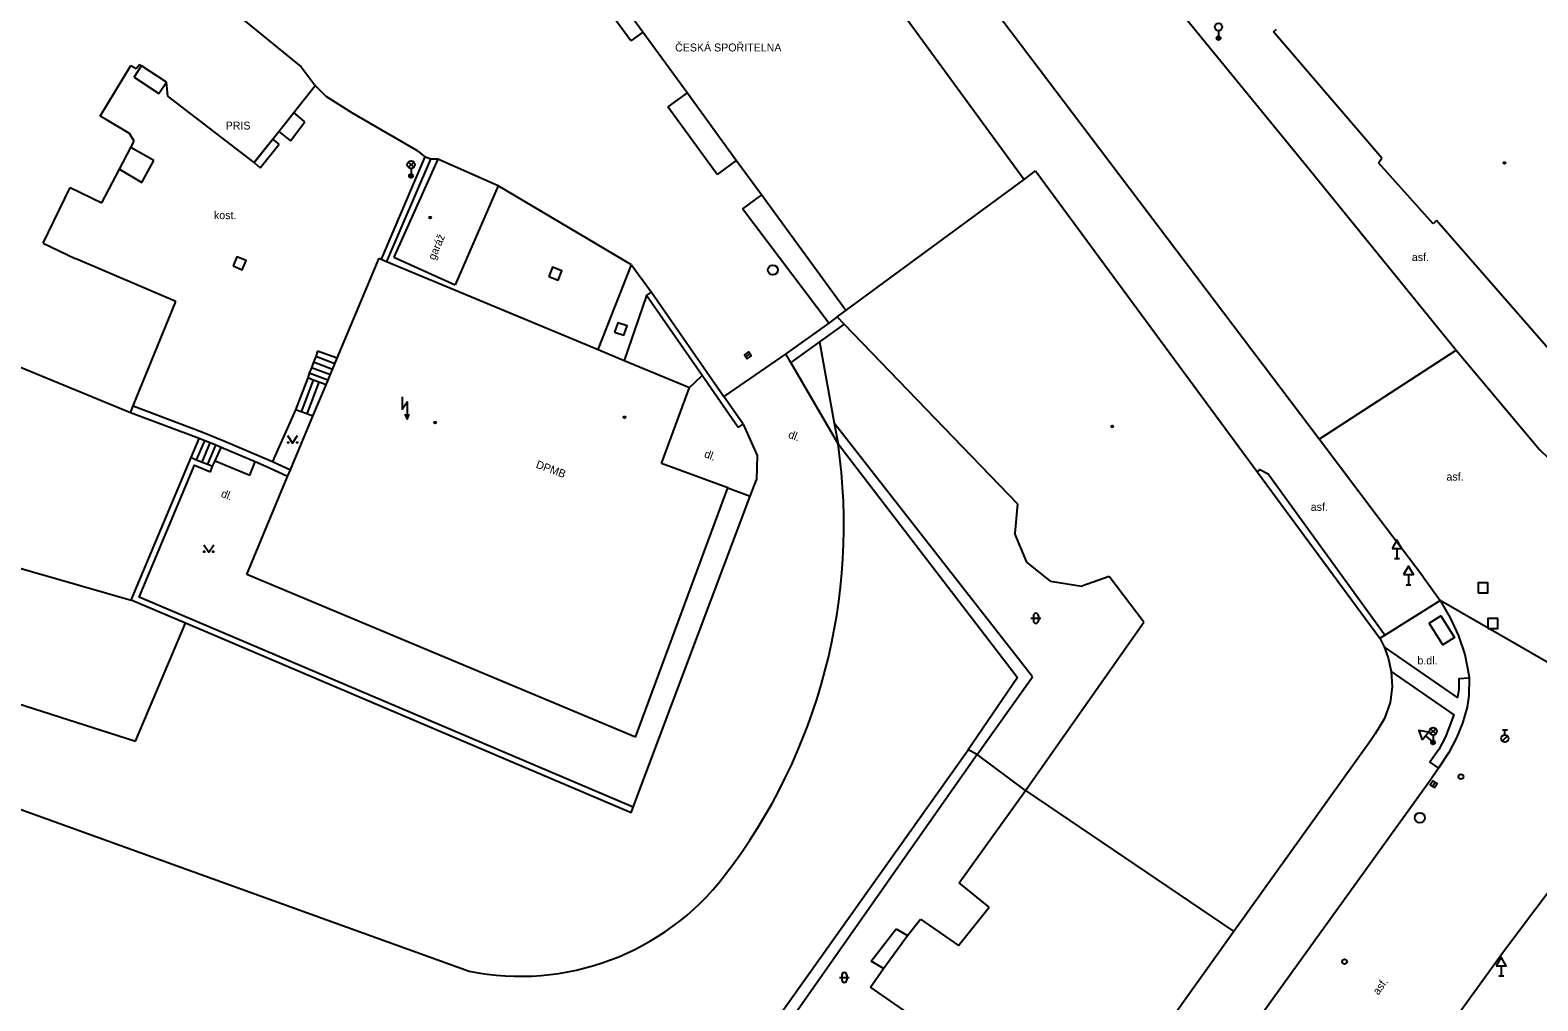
# Model space of a CAD drawing. Extents: x -599770 to -598493, y -1162076 to -1159209.
# Drawn here: x -599223.2 to -599147.3, y -1161433.6 to -1161384.7 of the extents above; entities that cross this region are included whole.
import ezdxf

# ---------------------------------------------------------------- set-up
doc = ezdxf.new("R2010")
doc.units = 0
doc.layers.add('Podklad', color=7, linetype='Continuous')

msp = doc.modelspace()

# ---------------------------------------------------------------- linework, layer by layer
at = {"layer": 'Podklad'}
for p, q in [((-599163.36, -1161384.765), (-599163.36, -1161385.14)), ((-599204.133, -1161391.64), (-599203.868, -1161391.375)), ((-599204.133, -1161391.375), (-599203.868, -1161391.64)), ((-599204, -1161391.695), (-599204, -1161392.07)), ((-599187.151, -1161401.174), (-599186.949, -1161401.026)), ((-599154.38, -1161410.821), (-599154.38, -1161411.33)), ((-599154.505, -1161411.33), (-599154.255, -1161411.33)), ((-599153.8, -1161412.141), (-599153.8, -1161412.65)), ((-599153.925, -1161412.65), (-599153.675, -1161412.65)), ((-599172.803, -1161414.338), (-599172.303, -1161414.338)), ((-599172.678, -1161414.213), (-599172.678, -1161414.463)), ((-599172.428, -1161414.213), (-599172.428, -1161414.463)), ((-599152.692, -1161420.16), (-599152.427, -1161419.895)), ((-599152.692, -1161419.895), (-599152.427, -1161420.16)), ((-599149.075, -1161419.953), (-599148.825, -1161419.953)), ((-599148.95, -1161420.203), (-599148.95, -1161419.953)), ((-599152.948, -1161420.261), (-599152.56, -1161420.59)), ((-599152.641, -1161420.685), (-599152.479, -1161420.495)), ((-599152.56, -1161420.215), (-599152.56, -1161420.59)), ((-599149.079, -1161420.526), (-599148.814, -1161420.261)), ((-599152.599, -1161422.795), (-599152.461, -1161422.585)), ((-599149.13, -1161431.831), (-599149.13, -1161432.34)), ((-599182.443, -1161432.418), (-599181.943, -1161432.418)), ((-599182.318, -1161432.293), (-599182.318, -1161432.543)), ((-599182.068, -1161432.293), (-599182.068, -1161432.543)), ((-599149.255, -1161432.34), (-599149.005, -1161432.34))]:
    msp.add_line(p, q, dxfattribs=at)
for points in [[(-599191.19, -1161352.2), (-599177.913, -1161368.369), (-599176.32, -1161370.31), (-599158.79, -1161391.75), (-599151.4, -1161400.84), (-599147.2, -1161405.85), (-599145.39, -1161407.58)], [(-599153.06, -1161412.26), (-599155.32, -1161409.26), (-599158.29, -1161405.32), (-599169.77, -1161390.15), (-599183.101, -1161372.518), (-599187.56, -1161366.62), (-599195.73, -1161355.8)], [(-599186.14, -1161374.45), (-599185.62, -1161375.163), (-599173.15, -1161392.26)], [(-599192.34, -1161384.84), (-599195.11, -1161381.05)], [(-599215.24, -1161381.92), (-599209.53, -1161386.58)], [(-599192.94, -1161385.28), (-599195.71, -1161381.49)], [(-599192.34, -1161384.84), (-599192.94, -1161385.28)], [(-599190.11, -1161387.89), (-599192.34, -1161384.84)], [(-599160.6, -1161384.82), (-599160.44, -1161384.68)], [(-599155.15, -1161391.18), (-599160.6, -1161384.82)], [(-599219.65, -1161389.07), (-599218.1, -1161386.52)], [(-599218.1, -1161386.52), (-599217.83, -1161386.67)], [(-599217.94, -1161387.1), (-599217.56, -1161386.53)], [(-599217.83, -1161386.67), (-599217.66, -1161386.46)], [(-599217.56, -1161386.53), (-599217.66, -1161386.46)], [(-599216.31, -1161387.36), (-599217.56, -1161386.53)], [(-599209.53, -1161386.58), (-599208.83, -1161387.52)], [(-599217.94, -1161387.1), (-599216.69, -1161387.92)], [(-599216.69, -1161387.92), (-599216.31, -1161387.36)], [(-599216.24, -1161388.06), (-599216.31, -1161387.36)], [(-599211.9, -1161391.4), (-599216.24, -1161388.06)], [(-599209.9, -1161388.88), (-599208.83, -1161387.52)], [(-599208.27, -1161388.08), (-599208.83, -1161387.52)], [(-599206.95, -1161388.91), (-599208.27, -1161388.08)], [(-599190.11, -1161387.89), (-599191.08, -1161388.6)], [(-599187.63, -1161391.29), (-599190.11, -1161387.89)], [(-599210.66, -1161389.84), (-599209.9, -1161388.88)], [(-599209.35, -1161389.35), (-599209.9, -1161388.88)], [(-599203.68, -1161390.81), (-599206.95, -1161388.91)], [(-599188.6, -1161392), (-599191.08, -1161388.6)], [(-599219.38, -1161389.22), (-599219.65, -1161389.07)], [(-599218.17, -1161389.94), (-599219.38, -1161389.22)], [(-599210.07, -1161390.31), (-599209.35, -1161389.35)], [(-599217.94, -1161390.32), (-599218.17, -1161389.94)], [(-599218.11, -1161390.64), (-599217.94, -1161390.32)], [(-599211.9, -1161391.4), (-599210.66, -1161389.84)], [(-599210.63, -1161390.48), (-599210.96, -1161390.22), (-599211.9, -1161391.4)], [(-599210.66, -1161389.84), (-599210.07, -1161390.31)], [(-599218.68, -1161391.73), (-599218.11, -1161390.64)], [(-599216.94, -1161391.29), (-599218.11, -1161390.64)], [(-599211.59, -1161391.66), (-599210.63, -1161390.48)], [(-599203.3, -1161391.12), (-599205.51, -1161396.26)], [(-599203.68, -1161390.81), (-599203.3, -1161391.12)], [(-599203.02, -1161391.23), (-599203.3, -1161391.12)], [(-599155.31, -1161391.42), (-599155.15, -1161391.18)], [(-599219.56, -1161393.43), (-599218.68, -1161391.73)], [(-599218.68, -1161391.73), (-599217.55, -1161392.4)], [(-599217.55, -1161392.4), (-599216.94, -1161391.29)], [(-599211.9, -1161391.4), (-599211.59, -1161391.66)], [(-599203.02, -1161391.23), (-599205.23, -1161396.38)], [(-599202.66, -1161391.23), (-599204.87, -1161396.17)], [(-599202.66, -1161391.23), (-599203.02, -1161391.23)], [(-599199.61, -1161392.57), (-599202.66, -1161391.23)], [(-599187.63, -1161391.29), (-599188.6, -1161392)], [(-599186.36, -1161393.03), (-599187.63, -1161391.29)], [(-599173.15, -1161392.26), (-599172.57, -1161391.82)], [(-599172.57, -1161391.82), (-599161.4, -1161406.98), (-599155.24, -1161415.34)], [(-599152.56, -1161394.48), (-599155.31, -1161391.42)], [(-599222.51, -1161395.46), (-599221.16, -1161392.65)], [(-599221.16, -1161392.65), (-599219.56, -1161393.43)], [(-599199.61, -1161392.57), (-599201.78, -1161397.56)], [(-599192.91, -1161396.55), (-599199.61, -1161392.57)], [(-599182.11, -1161398.84), (-599173.15, -1161392.26)], [(-599186.36, -1161393.03), (-599187.32, -1161393.73)], [(-599182.11, -1161398.84), (-599186.36, -1161393.03)], [(-599182.98, -1161399.48), (-599187.32, -1161393.73)], [(-599152.39, -1161394.32), (-599152.56, -1161394.48)], [(-599143.54, -1161404.47), (-599152.39, -1161394.32)], [(-599222.51, -1161395.46), (-599220.91, -1161396.23)], [(-599215.84, -1161398.4), (-599220.91, -1161396.23)], [(-599207.72, -1161401.25), (-599205.61, -1161396.22)], [(-599205.61, -1161396.22), (-599205.51, -1161396.26)], [(-599205.51, -1161396.26), (-599205.23, -1161396.38)], [(-599205.23, -1161396.38), (-599194.59, -1161400.81)], [(-599204.87, -1161396.17), (-599201.78, -1161397.56)], [(-599194.59, -1161400.81), (-599192.91, -1161396.55)], [(-599192.91, -1161396.55), (-599192.55, -1161397.03)], [(-599192.55, -1161397.03), (-599191.9, -1161397.93)], [(-599192.15, -1161398.1), (-599191.9, -1161397.93)], [(-599191.9, -1161397.93), (-599188.25, -1161403.17)], [(-599217.98, -1161403.65), (-599215.84, -1161398.4)], [(-599192.15, -1161398.1), (-599193.27, -1161401.36)], [(-599189.35, -1161402.12), (-599192.15, -1161398.1)], [(-599182.98, -1161399.48), (-599185.14, -1161401.03)], [(-599182.2, -1161399.53), (-599183.44, -1161400.42)], [(-599182.55, -1161399.17), (-599182.98, -1161399.48)], [(-599182.55, -1161399.17), (-599182.11, -1161398.84)], [(-599182.2, -1161399.53), (-599182.55, -1161399.17)], [(-599173.47, -1161408.57), (-599182.2, -1161399.53)], [(-599208.7, -1161400.89), (-599208.8, -1161401.17)], [(-599207.72, -1161401.25), (-599208.7, -1161400.89)], [(-599194.59, -1161400.81), (-599193.27, -1161401.36)], [(-599185.14, -1161401.03), (-599188.25, -1161403.17)], [(-599184.89, -1161401.46), (-599185.14, -1161401.03)], [(-599183.44, -1161400.42), (-599184.89, -1161401.46)], [(-599183.44, -1161400.42), (-599182.7, -1161404.52)], [(-599158.29, -1161405.32), (-599151.4, -1161400.84)], [(-599218.12, -1161403.99), (-599224.81, -1161401.24)], [(-599209.01, -1161401.73), (-599209.12, -1161402.01)], [(-599208.91, -1161401.45), (-599209.01, -1161401.73)], [(-599208.06, -1161402.08), (-599209.01, -1161401.73)], [(-599208.8, -1161401.17), (-599208.91, -1161401.45)], [(-599207.95, -1161401.81), (-599208.91, -1161401.45)], [(-599207.84, -1161401.53), (-599208.8, -1161401.17)], [(-599208.28, -1161402.59), (-599207.72, -1161401.25)], [(-599193.27, -1161401.36), (-599189.98, -1161402.73)], [(-599182.51, -1161405.56), (-599184.89, -1161401.46)], [(-599209.2, -1161402.24), (-599209.81, -1161403.84)], [(-599208.92, -1161402.35), (-599209.53, -1161403.95)], [(-599208.64, -1161402.45), (-599209.25, -1161404.05)], [(-599209.12, -1161402.01), (-599209.2, -1161402.24)], [(-599208.92, -1161402.35), (-599209.2, -1161402.24)], [(-599208.18, -1161402.36), (-599209.12, -1161402.01)], [(-599208.64, -1161402.45), (-599208.92, -1161402.35)], [(-599208.28, -1161402.59), (-599208.64, -1161402.45)], [(-599189.98, -1161402.73), (-599189.35, -1161402.12)], [(-599187.53, -1161404.74), (-599189.35, -1161402.12)], [(-599208.94, -1161404.17), (-599208.28, -1161402.59)], [(-599204.45, -1161403.19), (-599204.45, -1161403.815), (-599204.2, -1161403.44), (-599204.2, -1161404.315)], [(-599191.4, -1161406.54), (-599189.98, -1161402.73)], [(-599187.28, -1161404.57), (-599188.25, -1161403.17)], [(-599218.12, -1161403.99), (-599217.98, -1161403.65)], [(-599214.66, -1161405.29), (-599218.12, -1161403.99)], [(-599217.98, -1161403.65), (-599214.53, -1161404.95), (-599213.42, -1161405.4), (-599210.97, -1161406.44)], [(-599209.81, -1161403.84), (-599210.97, -1161406.44)], [(-599209.53, -1161403.95), (-599209.81, -1161403.84)], [(-599209.25, -1161404.05), (-599209.53, -1161403.95)], [(-599208.94, -1161404.17), (-599209.25, -1161404.05)], [(-599204.309, -1161404.071), (-599204.2, -1161404.315), (-599204.09, -1161404.071)], [(-599210.07, -1161406.86), (-599208.94, -1161404.17)], [(-599187.53, -1161404.74), (-599187.28, -1161404.57)], [(-599187.28, -1161404.57), (-599186.58, -1161406.15), (-599186.62, -1161407.37)], [(-599182.7, -1161404.52), (-599182.51, -1161405.56)], [(-599172.72, -1161417.28), (-599182.7, -1161404.52)], [(-599215.06, -1161406.25), (-599214.66, -1161405.29)], [(-599214.79, -1161406.36), (-599214.38, -1161405.4)], [(-599214.38, -1161405.4), (-599214.66, -1161405.29)], [(-599214.51, -1161406.48), (-599214.11, -1161405.51)], [(-599214.11, -1161405.51), (-599214.38, -1161405.4)], [(-599213.83, -1161405.63), (-599214.11, -1161405.51)], [(-599210.21, -1161405.145), (-599209.96, -1161405.52), (-599209.71, -1161405.145)], [(-599182.51, -1161405.56), (-599173.48, -1161417.32)], [(-599203.73, -1161419.54), (-599215.35, -1161414.59), (-599218.09, -1161413.43), (-599215.06, -1161406.25)], [(-599215.06, -1161406.25), (-599214.79, -1161406.36)], [(-599214.79, -1161406.36), (-599214.51, -1161406.48)], [(-599214.23, -1161406.59), (-599213.83, -1161405.63)], [(-599213.86, -1161406.41), (-599213.55, -1161405.74)], [(-599213.55, -1161405.74), (-599213.56, -1161405.74), (-599213.83, -1161405.63)], [(-599211.84, -1161406.47), (-599213.55, -1161405.74)], [(-599192.82, -1161423.85), (-599217.69, -1161413.27), (-599214.9, -1161406.64), (-599214.1, -1161406.97)], [(-599214.51, -1161406.48), (-599214.23, -1161406.59)], [(-599214.23, -1161406.59), (-599213.99, -1161406.69)], [(-599214.1, -1161406.97), (-599213.99, -1161406.69)], [(-599213.99, -1161406.69), (-599213.86, -1161406.41)], [(-599213.86, -1161406.41), (-599212.12, -1161407.13), (-599211.84, -1161406.47)], [(-599210.21, -1161407.2), (-599211.12, -1161406.78), (-599211.84, -1161406.47)], [(-599210.97, -1161406.44), (-599210.07, -1161406.86)], [(-599210.21, -1161407.2), (-599210.07, -1161406.86)], [(-599188.05, -1161407.78), (-599191.4, -1161406.54)], [(-599161.293, -1161406.863), (-599161.296, -1161406.866), (-599161.4, -1161406.98)], [(-599154.99, -1161415.18), (-599160.86, -1161407.08), (-599161.29, -1161406.86), (-599161.293, -1161406.863)], [(-599212.27, -1161412.14), (-599210.25, -1161407.29)], [(-599210.25, -1161407.29), (-599210.21, -1161407.2)], [(-599192.82, -1161423.85), (-599186.93, -1161408.19), (-599186.62, -1161407.37)], [(-599192.71, -1161420.32), (-599188.05, -1161407.78)], [(-599188.05, -1161407.78), (-599186.93, -1161408.19)], [(-599173.47, -1161408.57), (-599173.62, -1161410.07)], [(-599173.01, -1161411.52), (-599173.62, -1161410.07)], [(-599214.43, -1161410.635), (-599214.18, -1161411.01), (-599213.93, -1161410.635)], [(-599224.45, -1161411.6), (-599218.09, -1161413.43)], [(-599171.82, -1161412.47), (-599173.01, -1161411.52)], [(-599192.71, -1161420.32), (-599212.27, -1161412.14)], [(-599168.87, -1161412.24), (-599170.24, -1161412.72)], [(-599167.12, -1161414.53), (-599168.87, -1161412.24)], [(-599153.06, -1161412.26), (-599152.21, -1161413.45)], [(-599171.82, -1161412.47), (-599170.24, -1161412.72)], [(-599155.24, -1161415.34), (-599154.99, -1161415.18), (-599152.21, -1161413.45)], [(-599152.21, -1161413.45), (-599151.7, -1161414.32), (-599151.28, -1161415.22), (-599150.97, -1161416.16), (-599150.76, -1161417.2), (-599150.75, -1161417.35)], [(-599137.6, -1161419.42), (-599145.163, -1161417.511), (-599152.21, -1161413.45)], [(-599217.87, -1161420.52), (-599215.35, -1161414.59)], [(-599173.07, -1161423), (-599167.12, -1161414.53)], [(-599152.76, -1161414.58), (-599152.18, -1161414.21), (-599151.49, -1161415.31), (-599152.08, -1161415.67), (-599152.76, -1161414.58)], [(-599155.24, -1161415.34), (-599155.03, -1161415.77)], [(-599155.03, -1161415.77), (-599154.83, -1161416.33)], [(-599150.75, -1161417.35), (-599151.27, -1161417.38), (-599151.27, -1161417.9), (-599151.33, -1161418.32), (-599155.03, -1161415.77)], [(-599154.83, -1161416.33), (-599154.68, -1161417.01)], [(-599173.48, -1161417.32), (-599175.96, -1161420.96)], [(-599175.51, -1161421.2), (-599172.72, -1161417.28)], [(-599154.68, -1161417.01), (-599154.62, -1161417.79)], [(-599154.68, -1161417.01), (-599151.52, -1161419.19), (-599151.93, -1161420.3), (-599152.27, -1161420.94), (-599152.73, -1161421.58), (-599152.29, -1161421.88)], [(-599150.75, -1161417.35), (-599150.77, -1161418.23), (-599150.85, -1161418.82), (-599151.08, -1161419.62), (-599151.38, -1161420.36), (-599151.77, -1161421.1), (-599152.29, -1161421.88)], [(-599226.37, -1161417.8), (-599217.87, -1161420.52)], [(-599154.62, -1161417.79), (-599154.72, -1161418.57)], [(-599154.72, -1161418.57), (-599155, -1161419.38)], [(-599192.92, -1161424.13), (-599203.73, -1161419.54)], [(-599155, -1161419.38), (-599155.48, -1161420.16)], [(-599155.72, -1161420.51), (-599162.59, -1161430.1)], [(-599155.48, -1161420.16), (-599155.72, -1161420.51)], [(-599187.84, -1161437.67), (-599175.96, -1161420.96)], [(-599175.51, -1161421.2), (-599187.32, -1161438.02)], [(-599175.51, -1161421.2), (-599175.96, -1161420.96)], [(-599173.07, -1161423), (-599175.51, -1161421.2)], [(-599152.29, -1161421.88), (-599152.71, -1161422.51), (-599161.73, -1161435.03)], [(-599227.47, -1161422.58), (-599201.08, -1161432.1)], [(-599176.42, -1161427.65), (-599173.07, -1161423)], [(-599173.07, -1161423), (-599162.59, -1161430.1)], [(-599192.92, -1161424.13), (-599192.82, -1161423.85)], [(-599161.87, -1161449.1), (-599161.64, -1161448.77), (-599159.15, -1161445.36), (-599153.05, -1161436.68), (-599148.97, -1161431.05), (-599145.91, -1161426.98), (-599145.22, -1161426.08)], [(-599174.9, -1161428.87), (-599176.42, -1161427.65)], [(-599176.44, -1161430.8), (-599174.9, -1161428.87)], [(-599179.01, -1161430.31), (-599178.36, -1161429.48)], [(-599178.36, -1161429.48), (-599176.44, -1161430.8)], [(-599180.84, -1161431.6), (-599179.58, -1161429.97)], [(-599180.22, -1161431.96), (-599179.01, -1161430.31)], [(-599179.58, -1161429.97), (-599179.01, -1161430.31)], [(-599162.59, -1161430.1), (-599174.67, -1161447.02)], [(-599180.87, -1161432.91), (-599180.22, -1161431.96)], [(-599180.22, -1161431.96), (-599180.84, -1161431.6)], [(-599178.84, -1161434.31), (-599180.87, -1161432.91)]]:
    msp.add_lwpolyline(points, dxfattribs=at)
for points in [[(-599212.957, -1161396.603), (-599212.497, -1161396.797), (-599212.303, -1161396.337), (-599212.763, -1161396.142)], [(-599197.064, -1161397.131), (-599196.599, -1161397.314), (-599196.416, -1161396.849), (-599196.881, -1161396.666)], [(-599193.757, -1161399.936), (-599193.284, -1161400.097), (-599193.123, -1161399.624), (-599193.596, -1161399.463)], [(-599187.077, -1161401.275), (-599186.875, -1161401.127), (-599187.023, -1161400.925), (-599187.225, -1161401.073)], [(-599154.63, -1161410.821), (-599154.13, -1161410.821), (-599154.38, -1161410.388)], [(-599154.05, -1161412.141), (-599153.55, -1161412.141), (-599153.8, -1161411.708)], [(-599150.3, -1161413.06), (-599149.8, -1161413.06), (-599149.8, -1161412.56), (-599150.3, -1161412.56)], [(-599149.8, -1161414.85), (-599149.3, -1161414.85), (-599149.3, -1161414.35), (-599149.8, -1161414.35)], [(-599153.11, -1161420.451), (-599152.786, -1161420.07), (-599153.278, -1161419.98)], [(-599152.494, -1161422.863), (-599152.357, -1161422.654), (-599152.566, -1161422.517), (-599152.703, -1161422.726)], [(-599149.38, -1161431.831), (-599148.88, -1161431.831), (-599149.13, -1161431.398)]]:
    msp.add_lwpolyline(points, close=True, dxfattribs=at)
for centre, radius in [((-599163.36, -1161384.578), 0.188), ((-599163.36, -1161385.14), 0.1), ((-599163.36, -1161385.14), 0.0723), ((-599163.36, -1161385.14), 0.0438), ((-599204, -1161391.508), 0.188), ((-599148.97, -1161391.42), 0.045), ((-599148.97, -1161391.42), 0.0199), ((-599204, -1161392.07), 0.1), ((-599204, -1161392.07), 0.0723), ((-599204, -1161392.07), 0.0438), ((-599203.04, -1161394.17), 0.045), ((-599203.04, -1161394.17), 0.0199), ((-599185.79, -1161396.81), 0.25), ((-599202.79, -1161404.49), 0.045), ((-599202.79, -1161404.49), 0.0199), ((-599193.26, -1161404.22), 0.045), ((-599193.26, -1161404.22), 0.0199), ((-599168.71, -1161404.68), 0.045), ((-599168.71, -1161404.68), 0.0199), ((-599210.185, -1161405.495), 0.025), ((-599209.735, -1161405.495), 0.025), ((-599214.405, -1161410.985), 0.025), ((-599213.955, -1161410.985), 0.025), ((-599152.56, -1161420.027), 0.188), ((-599152.56, -1161420.59), 0.1), ((-599152.56, -1161420.59), 0.0723), ((-599152.56, -1161420.59), 0.0438), ((-599148.95, -1161420.39), 0.188), ((-599151.16, -1161422.31), 0.125), ((-599153.23, -1161424.38), 0.25), ((-599157.02, -1161431.62), 0.125)]:
    msp.add_circle(centre, radius, dxfattribs=at)
for centre, radius, start, end in [((-599211.142, -1161409.652), 28.923, 322.42197, 8.13244), ((-599172.553, -1161414.213), 0.125, 0, 180), ((-599172.553, -1161414.463), 0.125, 180, 0), ((-599198.506, -1161419.386), 12.972, 258.55349, 322.46092), ((-599182.193, -1161432.293), 0.125, 0, 180), ((-599182.193, -1161432.543), 0.125, 180, 0)]:
    msp.add_arc(centre, radius, start, end, dxfattribs=at)

# ---------------------------------------------------------------- texts
for s, p in [('ČESKÁ SPOŘITELNA', (-599190.71, -1161385.81)), ('PRIS', (-599213.33, -1161389.74)), ('kost.', (-599213.92, -1161394.25)), ('asf.', (-599153.63, -1161396.36)), ('asf.', (-599151.89, -1161407.41)), ('asf.', (-599158.72, -1161408.93)), ('b.dl.', (-599153.35, -1161416.66))]:
    msp.add_text(s, height=0.4, dxfattribs=at).set_placement(p)
for s, rotation, p in [('garáž', 66.94, (-599202.8, -1161396.34)), ('dl.', 339.61, (-599185.05, -1161405.24)), ('dl.', 339.61, (-599189.28, -1161406.22)), ('DPMB', 339.61, (-599197.75, -1161406.75)), ('dl.', 338.59, (-599213.6, -1161408.21)), ('asf.', 54.69, (-599155.31, -1161433.33))]:
    msp.add_text(s, height=0.4, rotation=rotation, dxfattribs=at).set_placement(p)

doc.saveas('drawing.dxf')
